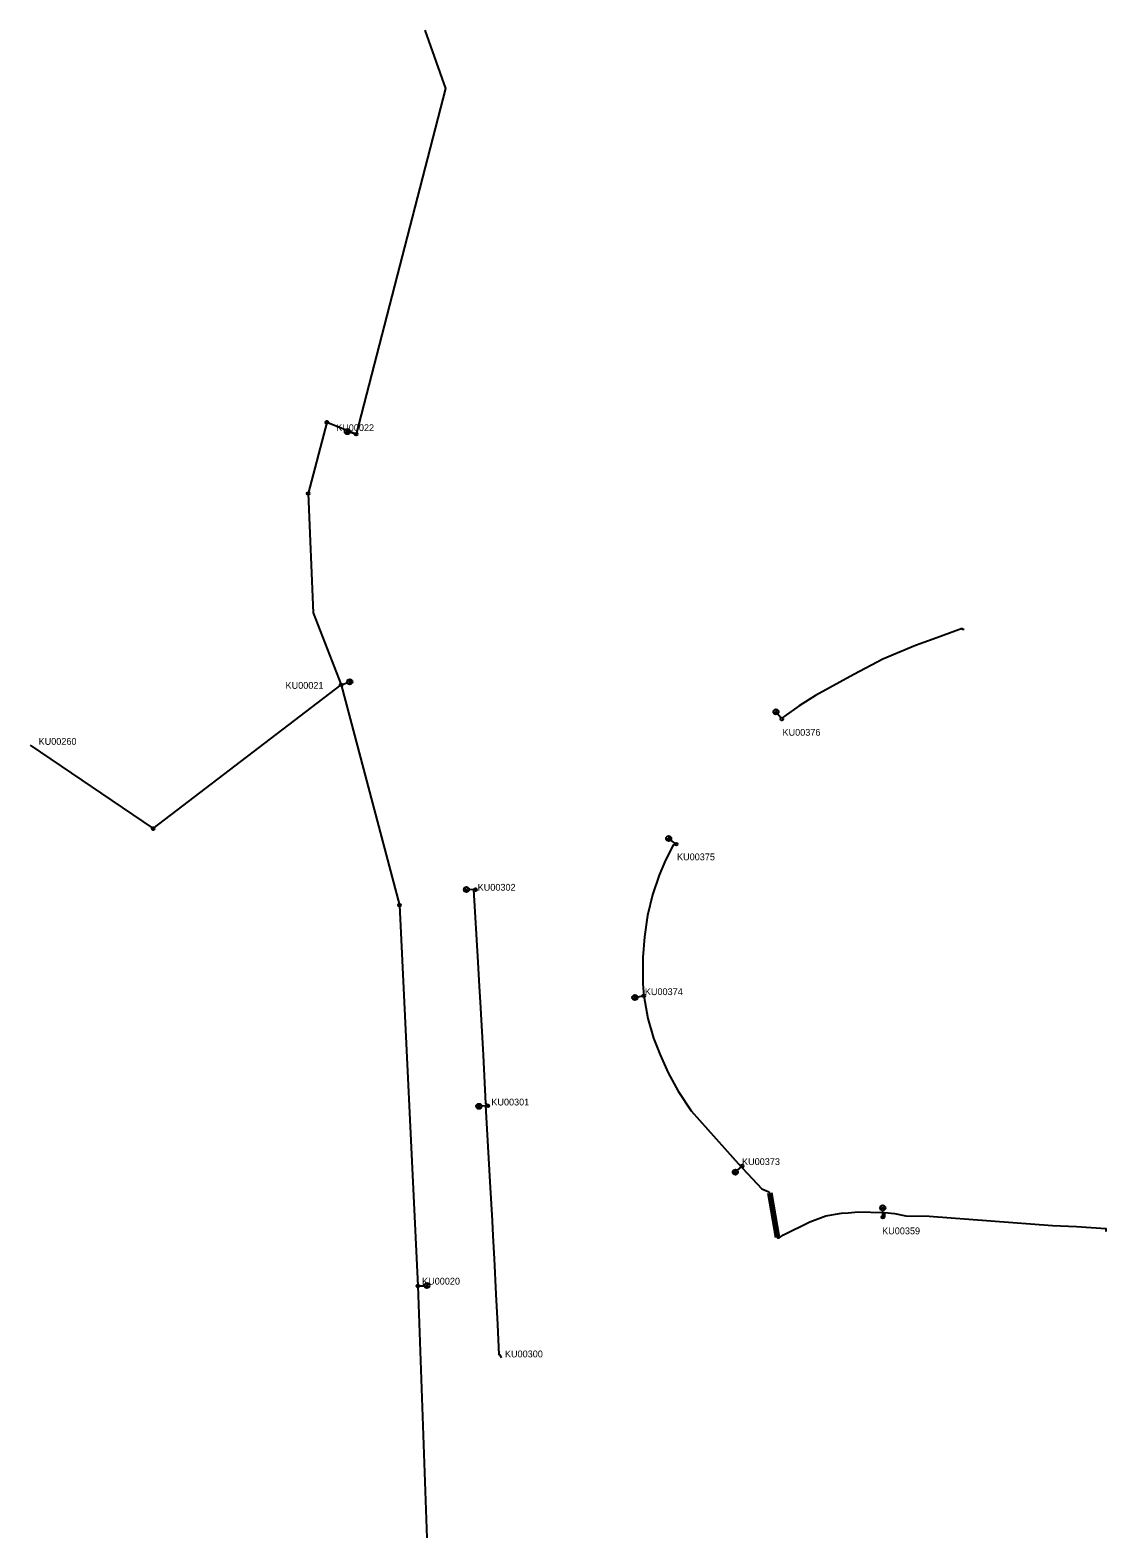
# Model space of a CAD drawing. Extents: x -727861 to -727623, y -1063232 to -1062899.
import ezdxf

# ---------------------------------------------------------------- set-up
doc = ezdxf.new("R2010")
doc.units = 0
for name, color, linetype in [('Chranicka', 7, 'Continuous'), ('Kabelove_vedeni_vrchni', 7, 'Continuous'), ('Kabelove_vedeni_zemni', 7, 'Continuous'), ('Pomocny_stozar', 7, 'Continuous'), ('Verejne_osvetleni', 7, 'Continuous'), ('Verejne_osvetleni_popis', 7, 'Continuous')]:
    doc.layers.add(name, color=color, linetype=linetype)

msp = doc.modelspace()

# ---------------------------------------------------------------- linework, layer by layer
at = {"layer": 'Chranicka'}
for points in [[(-727696.22, -1063165.4), (-727697.91, -1063155.61)], [(-727695.44, -1063165.26), (-727697.13, -1063155.47)]]:
    msp.add_lwpolyline(points, dxfattribs=at)
at = {"layer": 'Kabelove_vedeni_vrchni'}
for points in [[(-727773.61, -1062899.11), (-727769.06, -1062912), (-727788.79, -1062988.2)], [(-727788.79, -1062988.2), (-727795.23, -1062985.58), (-727799.37, -1063001.24), (-727798.29, -1063027.55), (-727792.09, -1063043.45)], [(-727860.68, -1063056.78), (-727833.58, -1063075.15), (-727792.09, -1063043.45)], [(-727792.09, -1063043.45), (-727779.2, -1063092.04), (-727775.21, -1063175.98)], [(-727775.21, -1063175.98), (-727773.21, -1063231.51)]]:
    msp.add_lwpolyline(points, dxfattribs=at)
at = {"layer": 'Kabelove_vedeni_zemni'}
for points in [[(-727654.66, -1063031.23), (-727655.08, -1063031.21), (-727655.13, -1063031.06), (-727660.71, -1063033.06), (-727665.45, -1063034.77), (-727672.61, -1063037.76), (-727679.04, -1063041.14), (-727687.46, -1063045.78), (-727691.09, -1063048.1), (-727694.37, -1063050.45), (-727694.9, -1063050.97)], [(-727718.22, -1063078.55), (-727718.83, -1063078.78), (-727720.55, -1063082.13), (-727721.97, -1063085.44), (-727723.39, -1063089.72), (-727724.51, -1063094.33), (-727725.19, -1063098.98), (-727725.55, -1063103.53), (-727725.53, -1063109.33), (-727725.32, -1063112.02)], [(-727762.43, -1063088.61), (-727762.43, -1063088.61), (-727762.63, -1063088.58), (-727762.92, -1063088.54), (-727761.97, -1063104.58), (-727761.65, -1063109.94), (-727761.45, -1063113.38), (-727760.86, -1063123.8), (-727760.79, -1063125.1), (-727760.22, -1063135.76), (-727760.04, -1063135.79), (-727759.7, -1063136.24)], [(-727725.32, -1063112.02), (-727724.45, -1063117.04), (-727723.21, -1063121.33), (-727721.76, -1063125.02), (-727720, -1063128.96), (-727717.73, -1063133.05), (-727714.93, -1063137.34), (-727703.87, -1063149.71), (-727703.66, -1063149.5)], [(-727756.72, -1063191.79), (-727756.97, -1063191.28), (-727757.25, -1063191.19), (-727757.57, -1063184.49), (-727757.9, -1063177.76), (-727758.3, -1063169.98), (-727758.57, -1063164.91), (-727758.74, -1063161.58), (-727759.23, -1063153.02), (-727760.2, -1063136.17), (-727759.9, -1063136.21), (-727759.7, -1063136.24)], [(-727703.66, -1063149.5), (-727703.45, -1063149.85), (-727703.61, -1063150.02), (-727699.3, -1063154.53), (-727697.8, -1063155.19), (-727697.52, -1063155.54), (-727695.83, -1063165.33), (-727695.49, -1063165.38), (-727694.56, -1063164.71), (-727688.75, -1063161.81), (-727685.23, -1063160.49), (-727681.77, -1063159.96), (-727680.25, -1063159.83), (-727678.05, -1063159.65), (-727672.56, -1063159.77), (-727672.63, -1063160.8)], [(-727672.63, -1063160.8), (-727672.22, -1063160.64), (-727672.16, -1063159.79), (-727670.05, -1063159.97), (-727667.54, -1063160.49), (-727662.4, -1063160.58), (-727635.18, -1063162.61), (-727629.9, -1063162.84), (-727623.44, -1063163.34), (-727623.48, -1063163.98)]]:
    msp.add_lwpolyline(points, dxfattribs=at)
at = {"layer": 'Pomocny_stozar'}
for centre in [(-727795.23, -1062985.58), (-727799.37, -1063001.24), (-727833.58, -1063075.15), (-727779.2, -1063092.04)]:
    msp.add_circle(centre, 0.305, dxfattribs=at)
at = {"layer": 'Verejne_osvetleni'}
for p, q in [((-727791.24, -1062987.9), (-727790.23, -1062987.35)), ((-727791.01, -1062987.12), (-727790.46, -1062988.13)), ((-727789.09, -1062988.11), (-727790.19, -1062987.79)), ((-727791.8, -1063043.35), (-727790.72, -1063042.96)), ((-727789.66, -1063043.01), (-727790.7, -1063042.52)), ((-727789.94, -1063042.25), (-727790.43, -1063043.28)), ((-727696.76, -1063049.36), (-727695.62, -1063049.46)), ((-727696.14, -1063048.84), (-727696.25, -1063049.98)), ((-727695.1, -1063050.73), (-727695.83, -1063049.85)), ((-727720.42, -1063077.43), (-727719.28, -1063077.26)), ((-727719.93, -1063076.78), (-727719.76, -1063077.91)), ((-727718.47, -1063078.37), (-727719.39, -1063077.69)), ((-727764.87, -1063088.98), (-727764.04, -1063088.18)), ((-727764.86, -1063088.17), (-727764.06, -1063088.99)), ((-727762.74, -1063088.61), (-727763.88, -1063088.59)), ((-727727.79, -1063112.05), (-727726.84, -1063112.71)), ((-727727.64, -1063112.85), (-727726.99, -1063111.91)), ((-727725.62, -1063112.07), (-727726.75, -1063112.28)), ((-727762.15, -1063135.98), (-727761.29, -1063136.74)), ((-727762.1, -1063136.79), (-727761.34, -1063135.93)), ((-727760, -1063136.26), (-727761.15, -1063136.32)), ((-727705.72, -1063150.85), (-727704.58, -1063150.9)), ((-727705.18, -1063151.45), (-727705.13, -1063150.3)), ((-727703.89, -1063149.71), (-727704.73, -1063150.48)), ((-727673.04, -1063158.37), (-727672.22, -1063159.18)), ((-727672.22, -1063158.37), (-727673.04, -1063159.18)), ((-727672.63, -1063160.49), (-727672.63, -1063159.35)), ((-727774.9, -1063175.96), (-727773.76, -1063175.91)), ((-727772.76, -1063176.28), (-727773.61, -1063175.5)), ((-727772.8, -1063175.47), (-727773.57, -1063176.31))]:
    msp.add_line(p, q, dxfattribs=at)
for centre, radius in [((-727790.74, -1062987.63), 0.574), ((-727788.79, -1062988.2), 0.306), ((-727792.09, -1063043.45), 0.306), ((-727790.18, -1063042.77), 0.574), ((-727696.19, -1063049.41), 0.574), ((-727694.9, -1063050.97), 0.306), ((-727719.85, -1063077.34), 0.574), ((-727718.22, -1063078.55), 0.306), ((-727764.46, -1063088.58), 0.574), ((-727762.43, -1063088.61), 0.306), ((-727727.31, -1063112.38), 0.574), ((-727725.32, -1063112.02), 0.306), ((-727761.72, -1063136.36), 0.574), ((-727759.7, -1063136.24), 0.306), ((-727705.15, -1063150.87), 0.574), ((-727703.66, -1063149.5), 0.306), ((-727672.63, -1063158.77), 0.574), ((-727672.63, -1063160.8), 0.306), ((-727775.21, -1063175.98), 0.306), ((-727773.19, -1063175.89), 0.574)]:
    msp.add_circle(centre, radius, dxfattribs=at)

# ---------------------------------------------------------------- texts
at = {"layer": 'Verejne_osvetleni_popis'}
for s, p in [('KU00022', (-727793.19, -1062987.5)), ('KU00021', (-727804.35, -1063044.32)), ('KU00376', (-727694.75, -1063054.67)), ('KU00260', (-727858.82, -1063056.67)), ('KU00375', (-727718.02, -1063082.12)), ('KU00302', (-727761.98, -1063088.83)), ('KU00374', (-727725.11, -1063111.85)), ('KU00301', (-727758.97, -1063136.18)), ('KU00373', (-727703.68, -1063149.32)), ('KU00359', (-727672.78, -1063164.58)), ('KU00020', (-727774.24, -1063175.67)), ('KU00300', (-727755.97, -1063191.71))]:
    msp.add_text(s, height=1.5, dxfattribs=at).set_placement(p)

doc.saveas('drawing.dxf')
